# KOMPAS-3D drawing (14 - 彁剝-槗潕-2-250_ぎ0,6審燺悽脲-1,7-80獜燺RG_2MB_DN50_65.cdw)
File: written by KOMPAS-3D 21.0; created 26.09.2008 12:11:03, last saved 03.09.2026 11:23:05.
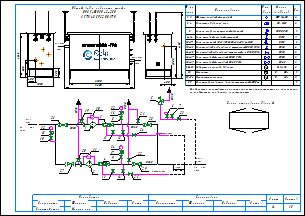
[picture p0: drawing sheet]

Sheets 1-2: A3, landscape

Document properties: Наименование: Макро:21; Автор: RaskoAdmin; Форматы листов документа: 2xA3; Полное имя файла: \\UR38nt01\Departments\КТО\КБ ПУРДГ\Заявки\Прайс-лист на типовые шкафы ГРПШ\ПРДГ_стандарт_20_03_2026\ПРДГ с RG_2MB\ПРДГ-ШУЭО-2-250_до0,6МПа_Рвых-1,7-80кПа_RG_2MB_DN50_65.cdw

Title block, sheet 1: Наименование: Пункт учета газа / ПУГ-Ш-400-Р / ЛГТИ.485922.001ТУ; designation: ЛГТИ.03.4411141; sheet number: 1; Количество листов документа: 2; organisation: ООО "ЭЛЬСТЕР Газэлектроника"; Форматы листов документа: A3; stored path: C:\Рабочие документы\Компас\ПУГ\Схема.cdw; Разработал: Устинов; Проверил: Кошкин; Утвердил: Кошкин
Title block, sheet 2: sheet number: 2; stored path: D:\Рабочие документы\Заявки\ПУРДГ\ПУРДГ-ШУЭО-2-100-Р 4411220.cdw; designation, second copy: ЛГТИ.03.4411141-

Views: Вид 1, Вид 2
Referenced files: wcvoit.frw
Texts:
  Normal
  Вход
  газа
  PDI
  Выход
  Р=     кПа
  DN65
  DN50
  DN20
  Импульс DN20
  ≥5DN
  HYSWLongFangSong
  № на
  схеме
  Усл.
  обозн.
  Марка
  (модель)
  Кол.
  Фильтр газовый фланцевый
  ФГ 16-50
  Регулятор давления газа
  RG/2MB
  Клапан предохранительный сбросной
  КПС DN20
  Кран шаровой газовый латунный
  DN15
  Кран кнопочный VE-РАСКО-НЗ-1,6-G1/2-М20
  Кран шаровой "под приварку" штуцерный DN20 PN16
  Кран шаровой "под приварку" штуцерный п/п DN20 PN16
  Кран шаровой фланцевый DN50 PN16
  Кран шаровой фланцевый DN65 PN16
  Индикатор перепада давления
  Delta 15
  Манометр
  Манометр-напоромер
  Электрообогреватель взрывозащищенный 400Вт
  0...     МПа
  0...     кПа
  Общий вид и габариты шкафа
  ПРДГ-ШУЭО-2-250
  Выход газа
  Вход газа
  Р=        МПа
  logo-rasko-ge.png
  Схема открывания дверей
  Предприятие изготовитель может заменять комплектующие на аналогичные,
  не ухудшающие заявленных характеристик.
  Должность
  Конструктор
  Фамилия
  Подпись
  Дата
  Согласовано
  Максимкин
  Лист
  Листов
  POLYLINE_STYLE_0.18_RGB_0_0_0
  POLYLINE_STYLE_0.50_RGB_0_0_0
  POLYLINE_STYLE_0.34_RGB_0_0_0
  PHANTOM_RGB_0_0_0_SC_1_THICK_0.18
  K5LT_THIN_RGB_0_0_0_THICK_0.18
  K5LT32769_RGB_0_0_0_THICK_0.18
  K5LT12_RGB_0_0_0_SC_1_THICK_0.18
  K5LT_DASHED_RGB_0_0_0_SC_1_THICK_0.18
  ACISOTGL_RGB_0_0_0_SC_0.8_THICK_0.25
  CONTINUOUS_RGB_0_127_31_THICK_0.3
  CONTINUOUS_RGB_0_0_255_THICK_0.35
  CONTINUOUS_RGB_255_0_0_THICK_0.35
  POLYLINE_STYLE_0.25_RGB_0_0_0
  CONTINUOUS_RGB_0_0_0_THICK_0.5
  POLYLINE_STYLE_0.35_RGB_0_0_255
  CONTINUOUS_RGB_0_0_0_THICK_0.4
  CONTINUOUS_RGB_0_0_0_THICK_0.35
  Без оформления
Dimensions and other numbers on the sheet: 1; 2; 3; 4; 5; 10; 27; 28; 29; 23; 8; 12; 19; 20; 21; 22; 25; 24; 30; 31; 15; 16; 26; 6; 7; 11; 14; 13; 33; 1, 2; 3, 4; 6-14; 9; 15-17; 18-23; 24-25; 26-27; 28-29; 30-31; 32; 33-34; 35; 400; 1050; 500; 305; 2300; 1565; 2600; 17; 34; 1000; 4130; 18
